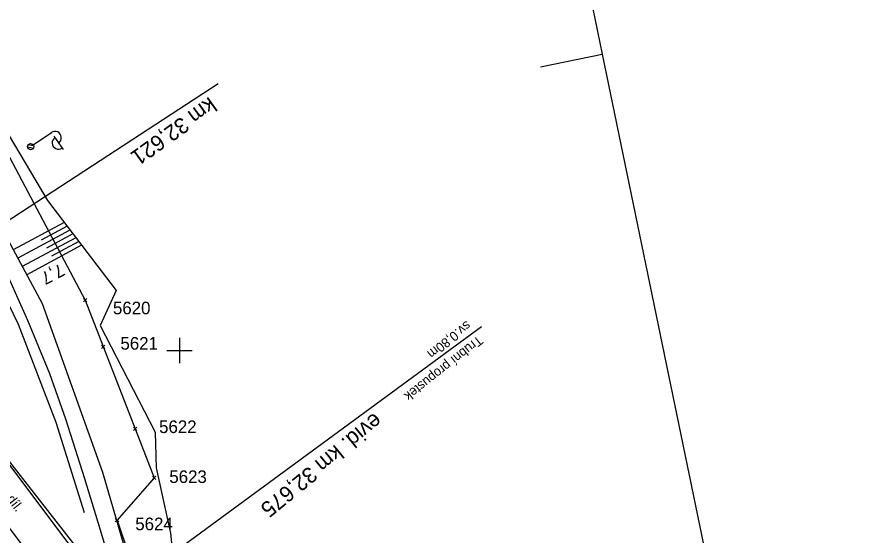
# Model space of a CAD drawing. Extents: x -804166 to -803706, y -1151030 to -1150147.
# Drawn here: x -803925.7 to -803790.5, y -1150429.4 to -1150347.1 of the extents above; entities that cross this region are included whole.
import ezdxf

# ---------------------------------------------------------------- set-up
doc = ezdxf.new("R2010")
doc.units = 0
for name, color, linetype in [('0381KM032-037P - Vrstva 1', 7, 'Continuous'), ('0381KM032-037P - Vrstva 19', 7, 'Continuous'), ('0381KM032-037P - Vrstva 23', 7, 'Continuous'), ('0381KM032-037P - Vrstva 25', 7, 'Continuous'), ('0381KM032-037P - Vrstva 3', 7, 'Continuous'), ('0381KM032-037P - Vrstva 4', 7, 'Continuous'), ('0381KM032-037P - Vrstva 48', 7, 'Continuous'), ('0381KM032-037P - Vrstva 49', 7, 'Continuous'), ('0381KM032-037P - Vrstva 51', 7, 'Continuous'), ('0381KM032-037P - Vrstva 55', 7, 'Continuous'), ('formát', 7, 'Continuous'), ('krizky_1000 - Vrstva 1', 7, 'Continuous'), ('szdc - hran DP', 7, 'Continuous'), ('szdc - szdc_cislo', 7, 'Continuous'), ('szdc - szdc_krizek', 7, 'Continuous')]:
    doc.layers.add(name, color=color, linetype=linetype)

msp = doc.modelspace()

# ---------------------------------------------------------------- linework, layer by layer
at = {"layer": '0381KM032-037P - Vrstva 1'}
msp.add_lwpolyline([(-804011.14, -1150262.39), (-804005.45, -1150273.41), (-803998.73, -1150284.85), (-803991.51, -1150295.63), (-803978.8, -1150312.77), (-803963.69, -1150332.99), (-803952.21, -1150348.36), (-803946.3, -1150356.39), (-803941.6, -1150363.14), (-803936.71, -1150370.83), (-803932.05, -1150378.84), (-803927.78, -1150386.91), (-803924.06, -1150395.18), (-803920.62, -1150403.65), (-803918.06, -1150410.86), (-803915.07, -1150420.32), (-803912.96, -1150427.25), (-803910.49, -1150435.34), (-803907.33, -1150445.05), (-803903.67, -1150454.38), (-803897.94, -1150464.6), (-803891.97, -1150476.6)], dxfattribs=at)
at = {"layer": '0381KM032-037P - Vrstva 19'}
msp.add_line((-803907.54, -1150436.87), (-803852.11, -1150396.22), dxfattribs=at)
at = {"layer": '0381KM032-037P - Vrstva 23'}
msp.add_line((-803916.52, -1150430.92), (-803932.91, -1150410.13), dxfattribs=at)
at = {"layer": '0381KM032-037P - Vrstva 25'}
for p, q in [((-803923.18, -1150367.4), (-803920.29, -1150365.43)), ((-803919.89, -1150366.01), (-803918.43, -1150368.16)), ((-803924.09, -1150367.73), (-803923.15, -1150367.91)), ((-803923.98, -1150367.37), (-803923.12, -1150367.53))]:
    msp.add_line(p, q, dxfattribs=at)
msp.add_circle((-803923.59, -1150367.68), 0.5, dxfattribs=at)
for centre, start, end in [((-803919.72, -1150366.26), 304.1945, 124.1945), ((-803919.17, -1150367.09), 123.4919, 304.8971)]:
    msp.add_arc(centre, 1, start, end, dxfattribs=at)
at = {"layer": '0381KM032-037P - Vrstva 3'}
msp.add_line((-803948.98, -1150393.6), (-803893.86, -1150357.66), dxfattribs=at)
at = {"layer": '0381KM032-037P - Vrstva 4'}
msp.add_lwpolyline([(-804015.09, -1150257.7), (-804005.61, -1150276.65), (-803997.81, -1150289.61), (-803985.99, -1150305.97), (-803963.83, -1150335.54), (-803947.69, -1150357.39), (-803941.6, -1150366.02), (-803933.49, -1150379.54), (-803925.57, -1150395.83), (-803919.57, -1150411.36), (-803915.11, -1150425.7)], dxfattribs=at)
at = {"layer": '0381KM032-037P - Vrstva 48'}
for p, q in [((-803918.27, -1150379.71), (-803926.34, -1150384.07)), ((-803917.81, -1150380.31), (-803921.9, -1150382.52)), ((-803917.35, -1150380.92), (-803925.63, -1150385.39)), ((-803916.89, -1150381.52), (-803921.08, -1150383.78)), ((-803916.43, -1150382.12), (-803924.92, -1150386.71)), ((-803915.96, -1150382.73), (-803920.26, -1150385.05)), ((-803915.5, -1150383.33), (-803924.2, -1150388.03))]:
    msp.add_line(p, q, dxfattribs=at)
at = {"layer": '0381KM032-037P - Vrstva 49'}
msp.add_line((-803929.73, -1150361.39), (-803920.94, -1150376.21), dxfattribs=at)
for points in [[(-804010.87, -1150255.86), (-804001.61, -1150274.67), (-803994.7, -1150286.68), (-803981.46, -1150304.36), (-803936.05, -1150366.09), (-803921.77, -1150392.54), (-803912.22, -1150419.28), (-803908.81, -1150430.91)], [(-803920.94, -1150376.21), (-803910.02, -1150390.51), (-803912.55, -1150396.06), (-803903.87, -1150412.95), (-803903.68, -1150418.64), (-803901.42, -1150428.97), (-803900.54, -1150437.64), (-803895.89, -1150448.56), (-803892.01, -1150457.3), (-803887.41, -1150463.6), (-803875.88, -1150484.91), (-803874.86, -1150484.5), (-803872.32, -1150492.5), (-803873, -1150496.55), (-803874.04, -1150498.95)]]:
    msp.add_lwpolyline(points, dxfattribs=at)
at = {"layer": '0381KM032-037P - Vrstva 51'}
msp.add_lwpolyline([(-804015.09, -1150257.7), (-804005.61, -1150276.65), (-803997.81, -1150289.61), (-803985.99, -1150305.97), (-803963.83, -1150335.54), (-803947.69, -1150357.39), (-803941.6, -1150366.02), (-803933.49, -1150379.54), (-803925.57, -1150395.83), (-803919.57, -1150411.36), (-803915.11, -1150425.7)], dxfattribs=at)
at = {"layer": '0381KM032-037P - Vrstva 55'}
msp.add_lwpolyline([(-803937.77, -1150413.78), (-803932.96, -1150410.23), (-803917.09, -1150431.3), (-803917.49, -1150431.6), (-803915.17, -1150434.66), (-803919.22, -1150437.65), (-803921.53, -1150434.55), (-803921.93, -1150434.85)], close=True, dxfattribs=at)
at = {"layer": 'formát'}
for p, q in [((-803875.43, -1150147.35), (-803832.97, -1150353.01)), ((-803842.77, -1150355.03), (-803832.97, -1150353.01)), ((-803842.77, -1150355.03), (-803832.97, -1150353.01)), ((-803832.97, -1150353.01), (-803790.51, -1150558.67))]:
    msp.add_line(p, q, dxfattribs=at)
at = {"layer": 'krizky_1000 - Vrstva 1'}
for points in [[(-803900, -1150398), (-803900, -1150402)], [(-803902, -1150400), (-803898, -1150400)]]:
    msp.add_lwpolyline(points, dxfattribs=at)
at = {"layer": 'szdc - hran DP'}
for p, q in [((-803936.41, -1150351.52), (-803914.94, -1150392.05)), ((-803914.94, -1150392.05), (-803912.08, -1150399.4)), ((-803912.08, -1150399.4), (-803907, -1150412.45)), ((-803907, -1150412.45), (-803903.99, -1150420.19)), ((-803903.99, -1150420.19), (-803909.89, -1150426.9)), ((-803909.89, -1150426.9), (-803907.15, -1150435.03))]:
    msp.add_line(p, q, dxfattribs=at)
at = {"layer": 'szdc - szdc_krizek'}
for p, q in [((-803914.68, -1150392.31), (-803915.21, -1150391.78)), ((-803915.21, -1150392.31), (-803914.68, -1150391.78)), ((-803911.82, -1150399.67), (-803912.35, -1150399.14)), ((-803912.35, -1150399.67), (-803911.82, -1150399.14)), ((-803906.73, -1150412.72), (-803907.27, -1150412.19)), ((-803907.27, -1150412.72), (-803906.73, -1150412.19)), ((-803903.72, -1150420.46), (-803904.26, -1150419.93)), ((-803904.26, -1150420.46), (-803903.72, -1150419.93)), ((-803909.62, -1150427.17), (-803910.16, -1150426.64)), ((-803910.16, -1150427.17), (-803909.62, -1150426.64))]:
    msp.add_line(p, q, dxfattribs=at)

# ---------------------------------------------------------------- texts
at = {"layer": '0381KM032-037P - Vrstva 19'}
for s, height, rotation, p in [('sv.0,80m', 1.5, 218.4095, (-803854.48, -1150395.22)), ('Trubní propustek', 1.5, 218.4095, (-803852.62, -1150397.57)), ('evid. km 32,675', 2.5, 219.3456, (-803869.1, -1150409.76))]:
    msp.add_text(s, height=height, rotation=rotation, dxfattribs=at).set_placement(p)
at = {"layer": '0381KM032-037P - Vrstva 23'}
msp.add_text('díl.', height=1.5, rotation=307.6769, dxfattribs=at).set_placement((-803927.46, -1150423.6))
at = {"layer": '0381KM032-037P - Vrstva 3'}
msp.add_text('km 32,621', height=2.5, rotation=215.7164, dxfattribs=at).set_placement((-803895.27, -1150359.69))
at = {"layer": '0381KM032-037P - Vrstva 48'}
msp.add_text('7,7', height=2, rotation=207.3698, dxfattribs=at).set_placement((-803918.88, -1150386.18))
at = {"layer": 'szdc - szdc_cislo'}
for s, p in [('5620', (-803910.54, -1150394.27)), ('5621', (-803909.35, -1150399.88)), ('5622', (-803903.22, -1150413.1)), ('5623', (-803901.6, -1150421.02)), ('5624', (-803907, -1150428.51))]:
    msp.add_text(s, height=2, dxfattribs=at).set_placement(p)

doc.saveas('drawing.dxf')
